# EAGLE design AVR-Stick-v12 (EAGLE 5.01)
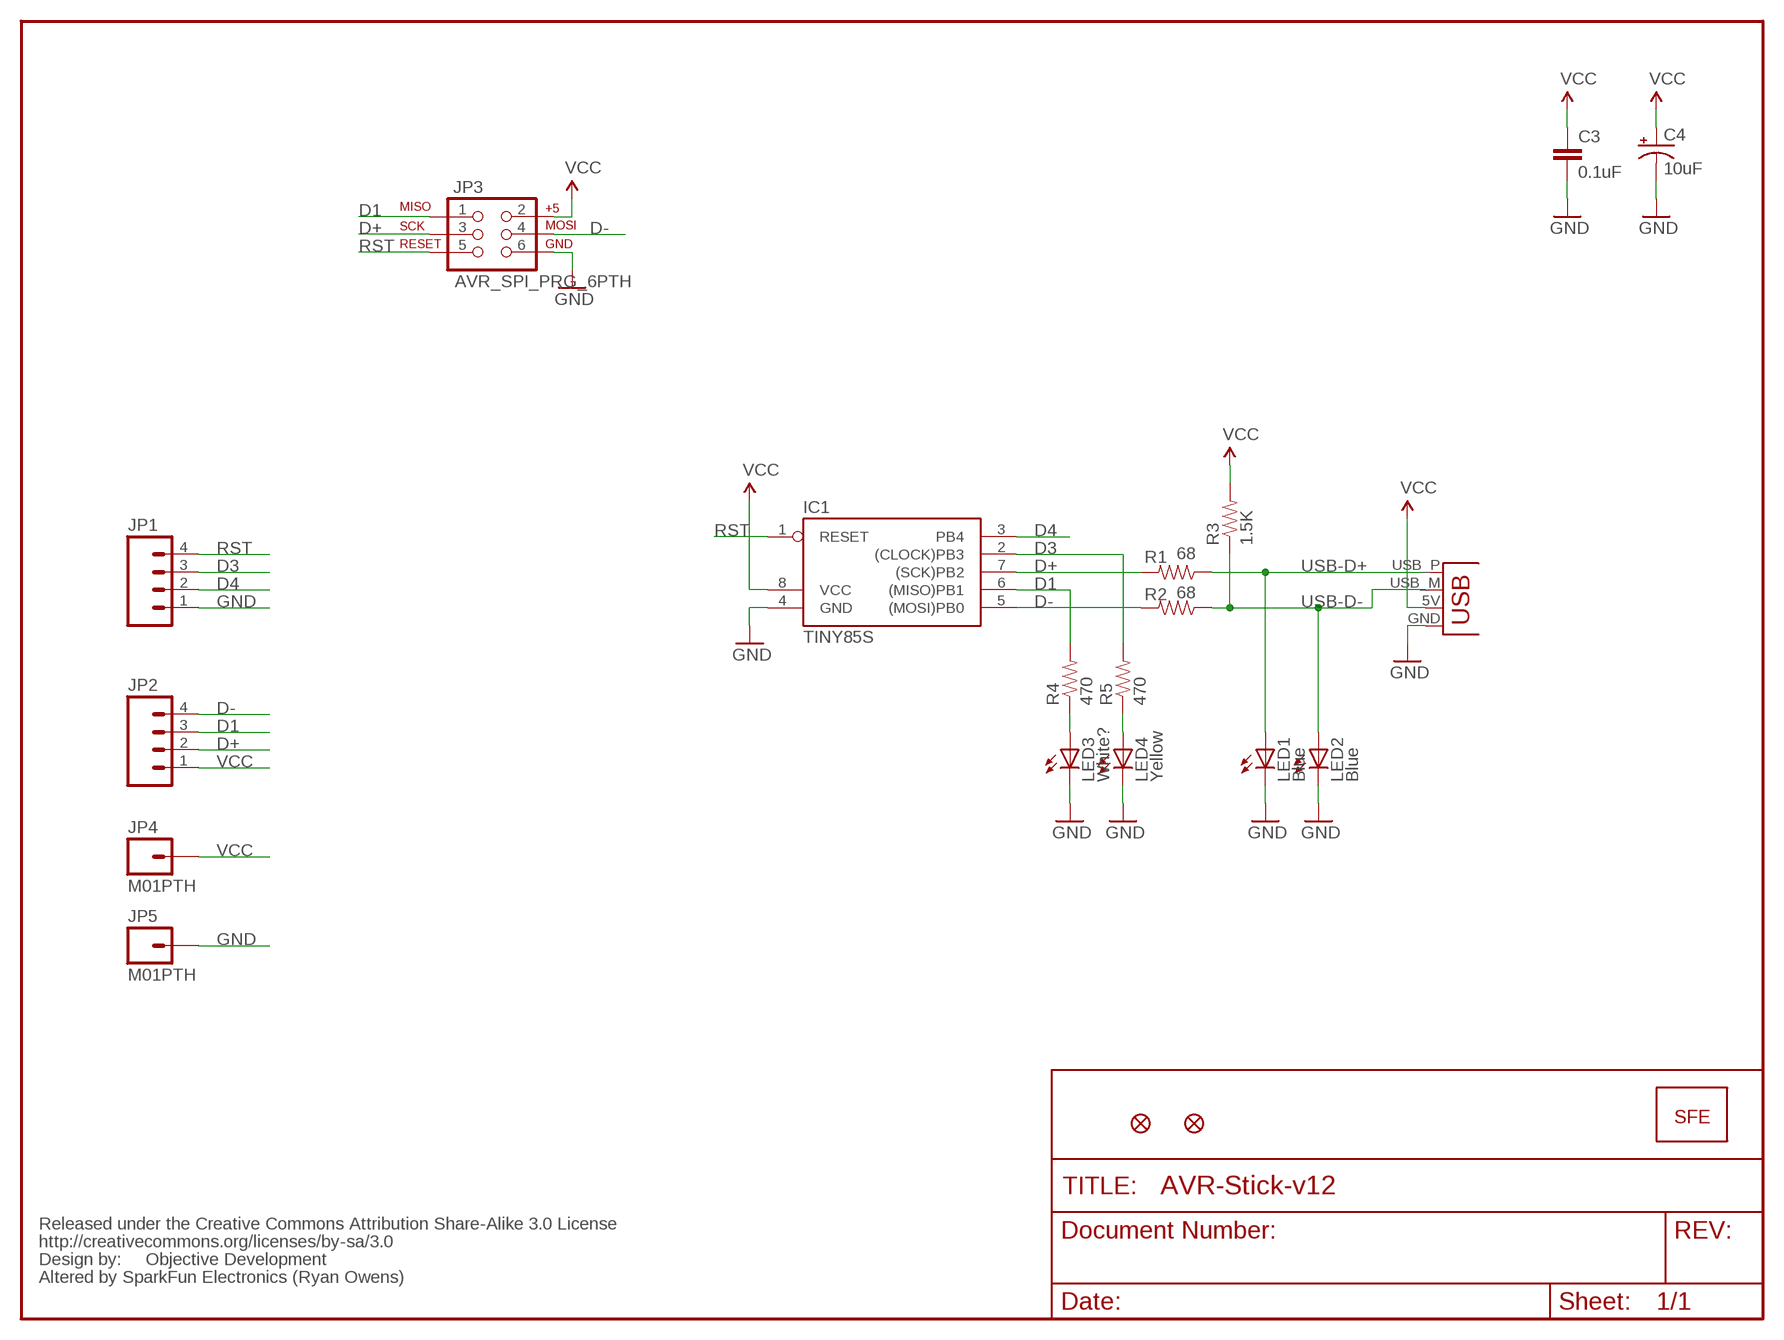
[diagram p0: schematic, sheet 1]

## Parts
C3  0.1uF  CAP0402-CAP  [0402-CAP]
C4  10uF  CAP_POL1206  [EIA3216]
IC1  TINY85S  [SOIC8]
JP1  M04PTH  [1X04]
JP2  M04PTH  [1X04]
JP3  AVR_SPI_PRG_6PTH  [2X3]
JP4  M01PTH  [1X01]
JP5  M01PTH  [1X01]
LED1  Blue  LED0603  [LED-0603]
LED2  Blue  LED0603  [LED-0603]
LED3  White?  LED0603  [LED-0603]
LED4  Yellow  LED0603  [LED-0603]
R1  68  RESISTOR0402-RES  [0402-RES]
R2  68  RESISTOR0402-RES  [0402-RES]
R3  1.5K  RESISTOR0402-RES  [0402-RES]
R4  470  RESISTOR0402-RES  [0402-RES]
R5  470  RESISTOR0402-RES  [0402-RES]
U$1  LOGO-SFESK  [SFE-LOGO-FLAME]
U$2  FIDUCIAL1X2  [FIDUCIAL-1X2]
U$3  FIDUCIAL1X2  [FIDUCIAL-1X2]
U$4  CREATIVE_COMMONS  [CREATIVE_COMMONS]
X1  USBPCB  [USB-A-PCB]

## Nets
D1: IC1.6((MISO)PB1) JP2.3 JP3.1 R4.2
D3: IC1.2((CLOCK)PB3) JP1.3 R5.2
D4: IC1.3(PB4) JP1.2
D+: IC1.7((SCK)PB2) JP2.2 JP3.3 R1.2
D-: IC1.5((MOSI)PB0) JP2.4 JP3.4 R2.2
GND: C3.2 C4.C(-) IC1.4(GND) JP1.1 JP3.6 JP5.1 LED1.C LED2.C LED3.C LED4.C X1.GND
N$7: LED3.A R4.1
N$9: LED4.A R5.1
RST: IC1.1(RESET) JP1.4 JP3.5
USB-D+: LED1.A R1.1 X1.USB_P(D+)
USB-D-: LED2.A R2.1 R3.1 X1.USB_M(D-)
VCC: C3.1 C4.A(+) IC1.8(VCC) JP2.1 JP3.2 JP4.1 R3.2 X1.5V(VBUS)

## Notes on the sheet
- Objective Development
- Altered by SparkFun Electronics (Ryan Owens)

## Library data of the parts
C3 = SparkFun:CAP: Capacitor
C4 = SparkFun:CAP_POL: Capacitor Polarized
IC1 = atmel:TINY85: MICROCONTROLLER 1K ROM 128 bytes RAM 128 bytes EEPROM
JP1 JP2 = SparkFun:M04: Header 4 Standard 4-pin 0.1" header. Use with straight break away headers (SKU : PRT-00116), right angle break away headers (PRT-00553), swiss pins (PRT-00743), machine pins (PRT-00117), and female headers (PRT-00115). Molex polarized connector foot print use with SKU : PRT-08231 with associated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
JP3 = SparkFun:AVR_SPI_PRG_6: AVR ISP 6 Pin This is the reduced ISP connector for AVR programming. Common on Arduino. This footprint will take up less PCB space and can be used with a 10-pin to 6-pin adapter such as SKU: BOB-08508
JP4 JP5 = SparkFun:M01: Header 1
LED1-LED4 = SparkFun:LED: LEDs
R1-R5 = SparkFun:RESISTOR: Resistor
U$1 = SparkFun:LOGO-SFE: Spark Fun Electronics PCB Logo
U$2 U$3 = SparkFun:FIDUCIAL: Fiducial Alignment Points
U$4 = SparkFun:CREATIVE_COMMONS
X1 = SparkFun:USB: USB Connectors USB-B-PTH is fully proven SKU : PRT-00139 USB-miniB is fully proven SKU : PRT-00587 USB-A-PCB is untested. USB-A-H is throughly reviewed, but untested. Spark Fun Electronics SKU : PRT-00437 USB-B-SMT is throughly reviewed, but untested. Needs silkscreen touching up. USB-A-S has not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

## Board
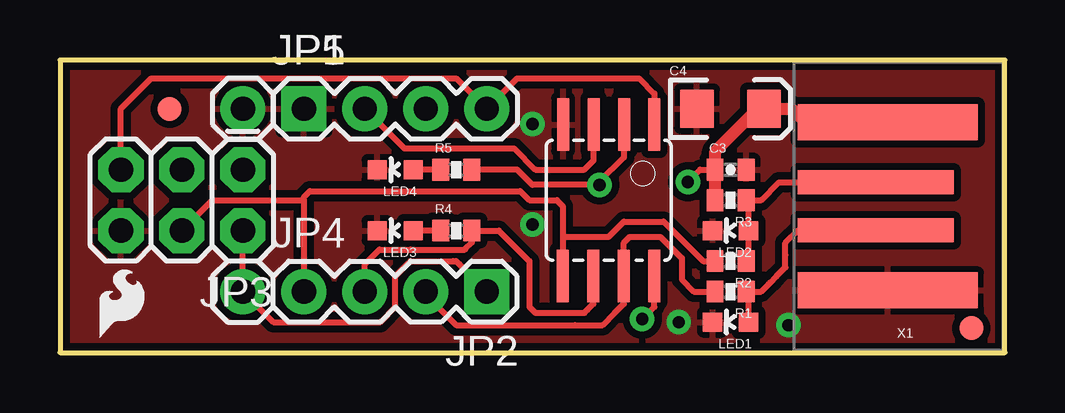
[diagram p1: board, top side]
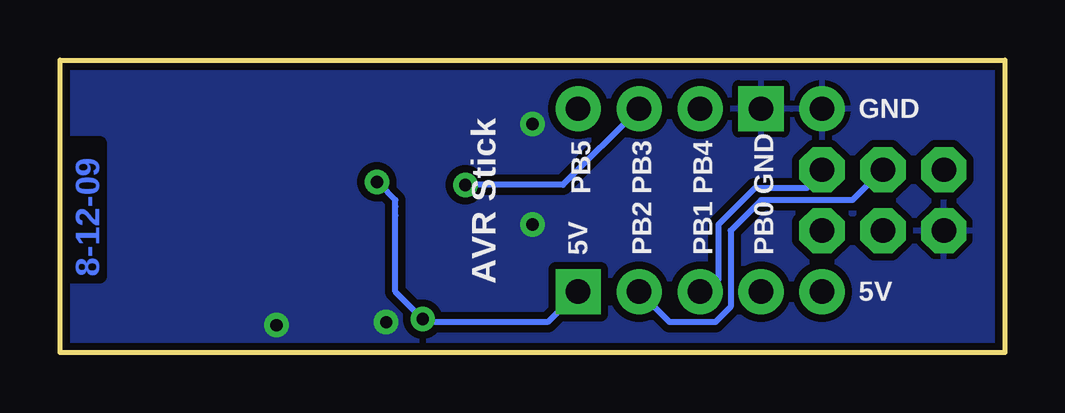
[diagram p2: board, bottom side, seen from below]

Size 39.37 x 12.19 mm. Coordinates in mm from the lower left corner, seen from the top.
Outline: 0,0 39.37,0 39.37,12.19 0,12.19 0,0
Copper layers (1*16): Top 0.035mm / dielectric 1.5mm / Bottom 0.035mm
Design rules "SparkFun": minimum track width 8mil, minimum drill 20mil, track to track 8mil, track to pad 8mil, pad to pad 8mil, via to via 8mil, smd to smd 8mil, copper to edge 10mil, drill to drill 8mil, minimum pad ring 12mil, minimum via ring 10mil, stop-mask expansion 4mil, vias tented up to drill 25mil, thermal gap 10mil

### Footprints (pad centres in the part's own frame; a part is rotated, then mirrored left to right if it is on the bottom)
0402-CAP = smd 0.7 x 0.9: 1 -0.65,0; 2 0.65,0
EIA3216 = smd 1.4 x 1.6: A 1.4,0; C -1.4,0
SOIC8 = smd 0.5 x 2.2: 1 -1.905,-3.154; 2 -0.645,-3.154; 3 0.625,-3.154; 4 1.895,-3.154; 5 1.905,3.154; 6 0.635,3.154; 7 -0.635,3.154; 8 -1.905,3.154
1X04 = drill 1.016 pad 1.88 square: 1 0,0 | drill 1.016 pad 1.88 round: 2 2.54,0; 3 5.08,0; 4 7.62,0
2X3 = drill 1.016 pad 1.88 octagon: 1 0,0; 2 0,2.54; 3 2.54,0; 4 2.54,2.54; 5 5.08,0; 6 5.08,2.54
1X01 = drill 1.016 pad 1.88 round: 1 0,0
LED-0603 = smd 0.8 x 0.8: A 0,-0.75; C 0,0.75
0402-RES = smd 0.7 x 0.9: 1 -0.65,0; 2 0.65,0
FIDUCIAL-1X2 = smd 1 x 1: 1 0,0
USB-A-PCB = smd 7.5 x 1.5: 5V -0.2,-3.5; GND -0.2,3.5 | smd 6.5 x 1: USB_M 0.3,-1; USB_P 0.3,1

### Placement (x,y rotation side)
C3  27.94,7.62 0 top
C4  27.94,10.16 0 top
IC1  22.86,6.35 180 top
JP1  10.16,10.16 0 top
JP2  17.78,2.54 180 top
JP3  7.62,7.62 180 top
JP4  7.62,2.54 0 top
JP5  7.62,10.16 0 top
LED1  27.94,1.27 90 top
LED2  27.94,5.08 90 top
LED3  13.97,5.08 90 top
LED4  13.97,7.62 90 top
R1  27.94,2.54 180 top
R2  27.94,3.81 180 top
R3  27.94,6.35 180 top
R4  16.51,5.08 0 top
R5  16.51,7.62 0 top
U$1  1.65,0.64 0 top
U$2  37.97,1.02 0 top
U$3  4.57,10.16 0 top
U$4  not placed on the board
X1  34.29,6.1 180 top

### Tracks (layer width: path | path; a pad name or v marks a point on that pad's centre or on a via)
D1
  Top 0.254: JP2.3 12.7,3.68 13.21,4.19 13.31,4.29 14.61,4.29 16.87,4.29 16.89,4.32 17.16,4.59 R4.2 18.29,5.08 19.56,3.81 19.56,2.03 19.56,1.91 19.68,1.78 19.81,1.65 19.94,1.65 21.84,1.65 21.97,1.78 22.22,2.03 IC1.6
  Bottom 0.254: JP3.1 7.62,7.49 8.26,6.86 10.41,6.86 11.05,6.22 11.94,5.33 11.94,3.81 11.94,3.05 12.45,2.54 JP2.3
D3  (via drill 0.51)
  Top 0.254: R5.2 19.05,7.62 19.68,6.99 v22.48,6.99 | v22.48,6.99 v22.49,7 | v22.48,6.99 22.48,7.11 23.5,8.14 IC1.2
  Bottom 0.254: JP1.3 18.41,6.99 v22.48,6.99
D4
  Top 0.254: IC1.3 22.23,8.01 21.84,7.62 19.81,7.62 18.92,8.51 14.35,8.51 14.22,8.64 JP1.2
D+
  Top 0.254: R1.2 26.42,2.54 25.91,3.05 25.91,3.94 25.02,4.83 23.75,4.83 23.5,4.57 IC1.7 23.5,2.03 23.11,1.65 22.61,1.14 21.46,1.14 16.51,1.14 15.37,2.29 15.24,2.41 JP2.2
  Bottom 0.254: JP3.3 6.35,6.35 10.16,6.35 11.43,5.08 11.43,1.91 12.06,1.27 13.97,1.27 JP2.2
D-
  Top 0.254: R2.2 26.8,3.81 25.15,5.46 23.5,5.46 22.86,4.83 20.95,4.83 | JP3.4 6.35,6.35 10.16,6.35 | 10.16,6.35 JP2.4 | 10.16,6.35 10.16,6.48 10.41,6.73 19.18,6.73 19.56,6.35 20.7,6.35 20.95,6.1 20.95,5.46 20.95,4.83 | 20.95,4.83 IC1.5
GND  (via drill 0.51)
  other vias: 19.68,9.53 19.68,5.33 30.35,1.14 25.78,1.27
  pour Bottom (isolate 0.305): 0,12.19 39.37,12.19 39.37,0 0,0
  pour Top (isolate 0.305): 0,0 0,12.19 39.37,12.19 39.37,0
N$7
  Top 0.254: R4.1 LED3.A
N$9
  Top 0.254: R5.1 LED4.A
RST
  Top 0.254: IC1.1 24.77,10.79 24.13,11.43 19.05,11.43 JP1.4 16.51,11.43 3.81,11.43 2.54,10.16 JP3.5
USB-D+
  Top 0.254: LED1.A 28.69,2.4 28.7,2.41 28.59,2.52 R1.1 29.21,2.54 29.53,2.86 29.59,2.92 29.84,3.17 30.23,3.56 30.23,4.06 30.23,4.57 30.75,5.1 X1.USB_P
USB-D-
  Top 0.254: R2.1 28.7,3.92 28.7,4.83 28.7,5.07 LED2.A 28.7,5.09 28.7,5.33 28.7,6.24 R3.1 29.21,6.35 29.96,7.1 X1.USB_M
VCC  (via drill 0.51)
  Top 0.254: IC1.8 24.77,1.91 v24.26,1.4 | JP2.1 16.64,3.68 16.51,3.81 16.38,3.81 14.61,3.81 14.48,3.68 13.97,3.17 13.97,1.91 13.33,1.27 8.89,1.27 JP4.1 JP3.2 | C3.1 26.67,7.62 v26.16,7.11
  Top 0.508: R3.2 C3.1 27.3,7.63 27.3,8.38 29.08,10.16 C4.A 30.35,10.16 30.48,10.16 31.04,9.6 X1.5V
  Bottom 0.254: JP2.1 19.05,1.27 24.13,1.27 v24.26,1.4 25.4,2.54 25.4,5.71 25.4,6.1 25.4,6.35 26.04,6.99 v26.16,7.11

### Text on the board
Bottom: 8-12-09
bPlace: GND | AVR Stick | GND | PB4 | PB3 | PB5 | PB0 | PB1 | PB2 | 5V | 5V
tValues: Objective Development | Altered by SparkFun Electronics (Ryan Owens)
